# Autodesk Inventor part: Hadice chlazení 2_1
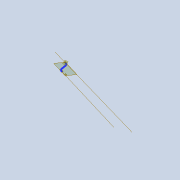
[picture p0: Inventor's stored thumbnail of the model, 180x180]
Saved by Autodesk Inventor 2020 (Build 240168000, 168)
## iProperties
Created: 2025-04
Part Number: Hadice chlazení 2_1
Material: Polyetylen, S nízkou hustotou
Document SubType Name: Modeling
Designer: doma
Density: 0.894 g/cm^3
Appearance: Modrá – nástěnná malba – lesklá
Author: doma
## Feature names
1. Tažení1
## Parameters: d4 = 5 mm, d5 = 5 mm, d8 = 8 mm, d9 = 0, d10 = 0, d11 = 38 deg
